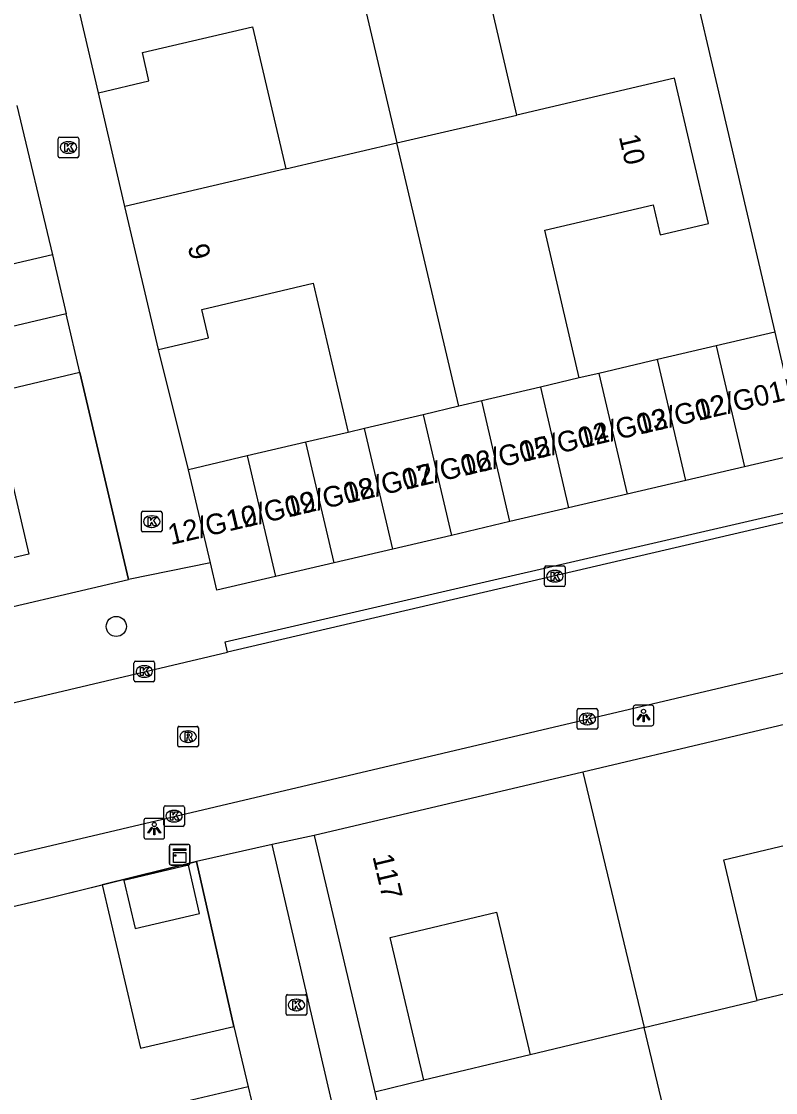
# Model space of a CAD drawing. Extents: x 162990 to 165007, y 383433 to 384336.
# Drawn here: x 164173.2 to 164209.8, y 384013 to 384065 of the extents above; entities that cross this region are included whole.
import ezdxf

# ---------------------------------------------------------------- set-up
doc = ezdxf.new("R2010")
doc.units = 0
for name, color, linetype in [('IMGEO_Boom', 7, 'Continuous'), ('IMGEO_Kast', 7, 'Continuous'), ('IMGEO_Kolk', 7, 'Continuous'), ('IMGEO_Lichtpunt', 7, 'Continuous'), ('IMGEO_Muur', 7, 'Continuous'), ('IMGEO_Pand', 7, 'Continuous'), ('IMGEO_Pand_nummerreeks', 7, 'Continuous'), ('IMGEO_Rijbaan_lokaal_open', 7, 'Continuous'), ('IMGEO_Rioolput', 7, 'Continuous'), ('IMGEO_Voetpad_open', 7, 'Continuous')]:
    doc.layers.add(name, color=color, linetype=linetype)

msp = doc.modelspace()

# ---------------------------------------------------------------- linework, layer by layer
at = {"layer": 'IMGEO_Boom'}
msp.add_circle((164177.761, 384035.63), 0.489, dxfattribs=at)
at = {"layer": 'IMGEO_Kast'}
for p, q in [((164180.337, 384024.129), (164180.337, 384024.97)), ((164180.337, 384024.97), (164180.337, 384024.129)), ((164180.412, 384025.054), (164181.253, 384025.054)), ((164181.253, 384025.054), (164180.412, 384025.054)), ((164181.337, 384024.979), (164181.337, 384024.138)), ((164181.337, 384024.138), (164181.337, 384024.979)), ((164181.262, 384024.054), (164180.421, 384024.054)), ((164180.421, 384024.054), (164181.262, 384024.054))]:
    msp.add_line(p, q, dxfattribs=at)
for points in [[(164180.532, 384024.844), (164181.132, 384024.844), (164181.132, 384024.759), (164180.532, 384024.759), (164180.532, 384024.844)], [(164180.532, 384024.669), (164181.132, 384024.669), (164181.132, 384024.18), (164180.532, 384024.18), (164180.532, 384024.669)]]:
    msp.add_lwpolyline(points, dxfattribs=at)
msp.add_circle((164180.616, 384024.518), 0.0377, dxfattribs=at)
for centre, start, end in [((164180.415, 384024.976), 92.4484, 184.2845), ((164180.415, 384024.976), 92.4484, 184.2845), ((164181.259, 384024.976), 2.4484, 94.2845), ((164181.259, 384024.976), 2.4484, 94.2845), ((164180.415, 384024.132), 182.4484, 274.2845), ((164180.415, 384024.132), 182.4484, 274.2845), ((164181.259, 384024.132), 272.4484, 4.2845), ((164181.259, 384024.132), 272.4484, 4.2845)]:
    msp.add_arc(centre, 0.0779, start, end, dxfattribs=at)
at = {"layer": 'IMGEO_Kolk'}
for p, q in [((164174.939, 384058.444), (164174.939, 384059.296)), ((164175.014, 384059.37), (164175.866, 384059.37)), ((164175.427, 384059.15), (164175.452, 384059.15)), ((164175.94, 384059.296), (164175.94, 384058.444)), ((164175.45, 384058.59), (164175.425, 384058.59)), ((164175.866, 384058.37), (164175.014, 384058.37)), ((164178.981, 384040.292), (164178.981, 384041.144)), ((164179.056, 384041.218), (164179.908, 384041.218)), ((164179.469, 384040.998), (164179.494, 384040.998)), ((164179.982, 384041.144), (164179.982, 384040.292)), ((164179.492, 384040.438), (164179.467, 384040.438)), ((164179.908, 384040.218), (164179.056, 384040.218)), ((164198.545, 384037.641), (164198.545, 384038.493)), ((164198.62, 384038.567), (164199.472, 384038.567)), ((164199.033, 384038.347), (164199.058, 384038.347)), ((164199.546, 384038.493), (164199.546, 384037.641)), ((164199.056, 384037.787), (164199.031, 384037.787)), ((164199.472, 384037.567), (164198.62, 384037.567)), ((164178.62, 384033.019), (164178.62, 384033.871)), ((164178.695, 384033.945), (164179.547, 384033.945)), ((164179.108, 384033.725), (164179.133, 384033.725)), ((164179.621, 384033.871), (164179.621, 384033.019)), ((164179.131, 384033.165), (164179.106, 384033.165)), ((164179.547, 384032.945), (164178.695, 384032.945)), ((164200.123, 384030.715), (164200.123, 384031.567)), ((164200.198, 384031.641), (164201.05, 384031.641)), ((164201.124, 384031.567), (164201.124, 384030.715)), ((164200.611, 384031.421), (164200.636, 384031.421)), ((164201.05, 384030.641), (164200.198, 384030.641)), ((164200.634, 384030.861), (164200.609, 384030.861)), ((164180.063, 384026.001), (164180.063, 384026.853)), ((164180.138, 384026.927), (164180.99, 384026.927)), ((164181.064, 384026.853), (164181.064, 384026.001)), ((164180.551, 384026.707), (164180.576, 384026.707)), ((164180.99, 384025.927), (164180.138, 384025.927)), ((164180.574, 384026.147), (164180.549, 384026.147)), ((164186.002, 384016.838), (164186.002, 384017.69)), ((164186.077, 384017.764), (164186.929, 384017.764)), ((164186.49, 384017.544), (164186.515, 384017.544)), ((164187.003, 384017.69), (164187.003, 384016.838)), ((164186.513, 384016.984), (164186.488, 384016.984)), ((164186.929, 384016.764), (164186.077, 384016.764))]:
    msp.add_line(p, q, dxfattribs=at)
for points in [[(164174.939, 384058.444), (164174.939, 384059.296)], [(164175.014, 384059.37), (164175.866, 384059.37)], [(164175.26, 384059.07), (164175.383, 384059.07), (164175.383, 384058.919), (164175.513, 384059.07), (164175.677, 384059.07), (164175.531, 384058.919), (164175.684, 384058.67), (164175.532, 384058.67), (164175.447, 384058.834), (164175.383, 384058.767), (164175.383, 384058.67), (164175.26, 384058.67), (164175.26, 384059.07)], [(164175.94, 384059.296), (164175.94, 384058.444)], [(164175.866, 384058.37), (164175.014, 384058.37)], [(164178.981, 384040.292), (164178.981, 384041.144)], [(164179.056, 384041.218), (164179.908, 384041.218)], [(164179.302, 384040.918), (164179.425, 384040.918), (164179.425, 384040.767), (164179.555, 384040.918), (164179.719, 384040.918), (164179.573, 384040.767), (164179.726, 384040.518), (164179.574, 384040.518), (164179.489, 384040.682), (164179.425, 384040.615), (164179.425, 384040.518), (164179.302, 384040.518), (164179.302, 384040.918)], [(164179.982, 384041.144), (164179.982, 384040.292)], [(164179.908, 384040.218), (164179.056, 384040.218)], [(164198.545, 384037.641), (164198.545, 384038.493)], [(164198.62, 384038.567), (164199.472, 384038.567)], [(164198.866, 384038.267), (164198.989, 384038.267), (164198.989, 384038.116), (164199.119, 384038.267), (164199.283, 384038.267), (164199.137, 384038.116), (164199.29, 384037.867), (164199.138, 384037.867), (164199.053, 384038.031), (164198.989, 384037.964), (164198.989, 384037.867), (164198.866, 384037.867), (164198.866, 384038.267)], [(164199.546, 384038.493), (164199.546, 384037.641)], [(164199.472, 384037.567), (164198.62, 384037.567)], [(164178.62, 384033.019), (164178.62, 384033.871)], [(164178.695, 384033.945), (164179.547, 384033.945)], [(164178.941, 384033.645), (164179.064, 384033.645), (164179.064, 384033.494), (164179.194, 384033.645), (164179.358, 384033.645), (164179.212, 384033.494), (164179.365, 384033.245), (164179.213, 384033.245), (164179.128, 384033.409), (164179.064, 384033.342), (164179.064, 384033.245), (164178.941, 384033.245), (164178.941, 384033.645)], [(164179.621, 384033.871), (164179.621, 384033.019)], [(164179.547, 384032.945), (164178.695, 384032.945)], [(164200.123, 384030.715), (164200.123, 384031.567)], [(164200.198, 384031.641), (164201.05, 384031.641)], [(164201.124, 384031.567), (164201.124, 384030.715)], [(164200.444, 384031.341), (164200.567, 384031.341), (164200.567, 384031.19), (164200.697, 384031.341), (164200.861, 384031.341), (164200.715, 384031.19), (164200.868, 384030.941), (164200.716, 384030.941), (164200.631, 384031.105), (164200.567, 384031.038), (164200.567, 384030.941), (164200.444, 384030.941), (164200.444, 384031.341)], [(164201.05, 384030.641), (164200.198, 384030.641)], [(164180.063, 384026.001), (164180.063, 384026.853)], [(164180.138, 384026.927), (164180.99, 384026.927)], [(164181.064, 384026.853), (164181.064, 384026.001)], [(164180.384, 384026.627), (164180.507, 384026.627), (164180.507, 384026.476), (164180.637, 384026.627), (164180.801, 384026.627), (164180.655, 384026.476), (164180.808, 384026.227), (164180.656, 384026.227), (164180.571, 384026.391), (164180.507, 384026.324), (164180.507, 384026.227), (164180.384, 384026.227), (164180.384, 384026.627)], [(164180.99, 384025.927), (164180.138, 384025.927)], [(164186.002, 384016.838), (164186.002, 384017.69)], [(164186.077, 384017.764), (164186.929, 384017.764)], [(164186.323, 384017.464), (164186.446, 384017.464), (164186.446, 384017.313), (164186.576, 384017.464), (164186.74, 384017.464), (164186.594, 384017.313), (164186.747, 384017.064), (164186.595, 384017.064), (164186.51, 384017.228), (164186.446, 384017.161), (164186.446, 384017.064), (164186.323, 384017.064), (164186.323, 384017.464)], [(164187.003, 384017.69), (164187.003, 384016.838)], [(164186.929, 384016.764), (164186.077, 384016.764)]]:
    msp.add_lwpolyline(points, dxfattribs=at)
for centre, start, end in [((164175.016, 384059.294), 91.552, 178.448), ((164175.016, 384059.294), 91.552, 178.448), ((164175.864, 384059.294), 1.552, 88.448), ((164175.864, 384059.294), 1.552, 88.448), ((164175.016, 384058.446), 181.552, 268.448), ((164175.016, 384058.446), 181.552, 268.448), ((164175.864, 384058.446), 271.552, 358.448), ((164175.864, 384058.446), 271.552, 358.448), ((164179.058, 384041.142), 91.552, 178.448), ((164179.058, 384041.142), 91.552, 178.448), ((164179.906, 384041.142), 1.552, 88.448), ((164179.906, 384041.142), 1.552, 88.448), ((164179.058, 384040.294), 181.552, 268.448), ((164179.058, 384040.294), 181.552, 268.448), ((164179.906, 384040.294), 271.552, 358.448), ((164179.906, 384040.294), 271.552, 358.448), ((164198.622, 384038.491), 91.552, 178.448), ((164198.622, 384038.491), 91.552, 178.448), ((164199.47, 384038.491), 1.552, 88.448), ((164199.47, 384038.491), 1.552, 88.448), ((164198.622, 384037.643), 181.552, 268.448), ((164198.622, 384037.643), 181.552, 268.448), ((164199.47, 384037.643), 271.552, 358.448), ((164199.47, 384037.643), 271.552, 358.448), ((164178.697, 384033.869), 91.552, 178.448), ((164178.697, 384033.869), 91.552, 178.448), ((164179.545, 384033.869), 1.552, 88.448), ((164179.545, 384033.869), 1.552, 88.448), ((164178.697, 384033.021), 181.552, 268.448), ((164178.697, 384033.021), 181.552, 268.448), ((164179.545, 384033.021), 271.552, 358.448), ((164179.545, 384033.021), 271.552, 358.448), ((164200.2, 384031.565), 91.552, 178.448), ((164200.2, 384031.565), 91.552, 178.448), ((164201.048, 384031.565), 1.552, 88.448), ((164201.048, 384031.565), 1.552, 88.448), ((164200.2, 384030.717), 181.552, 268.448), ((164200.2, 384030.717), 181.552, 268.448), ((164201.048, 384030.717), 271.552, 358.448), ((164201.048, 384030.717), 271.552, 358.448), ((164180.14, 384026.851), 91.552, 178.448), ((164180.14, 384026.851), 91.552, 178.448), ((164180.988, 384026.851), 1.552, 88.448), ((164180.988, 384026.851), 1.552, 88.448), ((164180.14, 384026.003), 181.552, 268.448), ((164180.14, 384026.003), 181.552, 268.448), ((164180.988, 384026.003), 271.552, 358.448), ((164180.988, 384026.003), 271.552, 358.448), ((164186.079, 384017.688), 91.552, 178.448), ((164186.079, 384017.688), 91.552, 178.448), ((164186.927, 384017.688), 1.552, 88.448), ((164186.927, 384017.688), 1.552, 88.448), ((164186.079, 384016.84), 181.552, 268.448), ((164186.079, 384016.84), 181.552, 268.448), ((164186.927, 384016.84), 271.552, 358.448), ((164186.927, 384016.84), 271.552, 358.448)]:
    msp.add_arc(centre, 0.0765, start, end, dxfattribs=at)
for centre, major_axis, ratio, start_param, end_param in [((164175.426, 384058.87), (-0.387, 0.002), 0.722429, 4.712389, 7.853982), ((164175.451, 384058.87), (-0.39, 0.002), 0.717154, 1.570796, 4.712389), ((164179.468, 384040.718), (-0.387, 0.002), 0.722429, 4.712389, 7.853982), ((164179.493, 384040.718), (-0.39, 0.002), 0.717154, 1.570796, 4.712389), ((164199.032, 384038.067), (-0.387, 0.002), 0.722429, 4.712389, 7.853982), ((164199.057, 384038.067), (-0.39, 0.002), 0.717154, 1.570796, 4.712389), ((164179.107, 384033.445), (-0.387, 0.002), 0.722429, 4.712389, 7.853982), ((164179.132, 384033.445), (-0.39, 0.002), 0.717154, 1.570796, 4.712389), ((164200.61, 384031.141), (-0.387, 0.002), 0.722429, 4.712389, 7.853982), ((164200.635, 384031.141), (-0.39, 0.002), 0.717154, 1.570796, 4.712389), ((164180.55, 384026.427), (-0.387, 0.002), 0.722429, 4.712389, 7.853982), ((164180.575, 384026.427), (-0.39, 0.002), 0.717154, 1.570796, 4.712389), ((164186.489, 384017.264), (-0.387, 0.002), 0.722429, 4.712389, 7.853982), ((164186.514, 384017.264), (-0.39, 0.002), 0.717154, 1.570796, 4.712389)]:
    msp.add_ellipse(centre, major_axis=major_axis, ratio=ratio, start_param=start_param, end_param=end_param, dxfattribs=at)
at = {"layer": 'IMGEO_Lichtpunt'}
for p, q in [((164202.851, 384031.711), (164202.851, 384030.904)), ((164202.851, 384031.711), (164202.851, 384030.904)), ((164203.753, 384031.806), (164202.945, 384031.806)), ((164203.753, 384031.806), (164202.945, 384031.806)), ((164203.847, 384030.904), (164203.847, 384031.711)), ((164203.847, 384030.904), (164203.847, 384031.711)), ((164202.945, 384030.81), (164203.753, 384030.81)), ((164202.945, 384030.81), (164203.753, 384030.81)), ((164180.007, 384026.317), (164179.199, 384026.317)), ((164180.007, 384026.317), (164179.199, 384026.317)), ((164179.105, 384026.222), (164179.105, 384025.415)), ((164179.105, 384026.222), (164179.105, 384025.415)), ((164180.101, 384025.415), (164180.101, 384026.222)), ((164180.101, 384025.415), (164180.101, 384026.222)), ((164179.199, 384025.321), (164180.007, 384025.321)), ((164179.199, 384025.321), (164180.007, 384025.321))]:
    msp.add_line(p, q, dxfattribs=at)
for points in [[(164203.225, 384031.375), (164203.264, 384031.347), (164203.076, 384031.085), (164203.038, 384031.112), (164203.225, 384031.375)], [(164203.327, 384031.327), (164203.374, 384031.327), (164203.374, 384031.005), (164203.327, 384031.005), (164203.327, 384031.327)], [(164203.437, 384031.347), (164203.475, 384031.374), (164203.662, 384031.112), (164203.623, 384031.084), (164203.437, 384031.347)], [(164179.479, 384025.886), (164179.518, 384025.858), (164179.33, 384025.596), (164179.292, 384025.623), (164179.479, 384025.886)], [(164179.581, 384025.838), (164179.628, 384025.838), (164179.628, 384025.516), (164179.581, 384025.516), (164179.581, 384025.838)], [(164179.691, 384025.858), (164179.729, 384025.885), (164179.916, 384025.623), (164179.877, 384025.595), (164179.691, 384025.858)]]:
    msp.add_lwpolyline(points, dxfattribs=at)
for centre in [(164203.35, 384031.509), (164179.604, 384026.02)]:
    msp.add_circle(centre, 0.0994, dxfattribs=at)
for centre, start, end in [((164202.945, 384031.711), 90, 180), ((164202.945, 384031.711), 90, 180), ((164203.753, 384031.711), 0, 90), ((164203.753, 384031.711), 0, 90), ((164202.945, 384030.904), 180, 270), ((164202.945, 384030.904), 180, 270), ((164203.753, 384030.904), 270, 0), ((164203.753, 384030.904), 270, 360), ((164179.199, 384026.222), 90, 180), ((164179.199, 384026.222), 90, 180), ((164180.007, 384026.222), 0, 90), ((164180.007, 384026.222), 0, 90), ((164179.199, 384025.415), 180, 270), ((164179.199, 384025.415), 180, 270), ((164180.007, 384025.415), 270, 0), ((164180.007, 384025.415), 270, 360)]:
    msp.add_arc(centre, 0.0946, start, end, dxfattribs=at)
at = {"layer": 'IMGEO_Muur'}
for points in [[(164172.928, 384060.907), (164174.66, 384053.664)], [(164208.559, 384054.87), (164209.723, 384049.905)], [(164175.996, 384047.946), (164178.35, 384037.909)], [(164173.854, 384022.308), (164181.656, 384024.223), (164183.473, 384016.224)]]:
    msp.add_lwpolyline(points, dxfattribs=at)
at = {"layer": 'IMGEO_Pand'}
for points in [[(164197.205, 384060.438), (164195.579, 384067.39), (164200.842, 384068.621), (164201.182, 384067.168), (164203.595, 384067.732), (164201.976, 384074.657), (164194.291, 384072.86)], [(164188.442, 384071.542), (164191.376, 384059.087)], [(164176.898, 384061.524), (164175.266, 384068.505)], [(164176.898, 384061.524), (164179.347, 384062.097), (164179.025, 384063.472), (164184.375, 384064.723), (164185.985, 384057.837)], [(164200.231, 384047.685), (164198.554, 384054.858), (164203.824, 384056.091), (164204.164, 384054.636), (164206.499, 384055.182), (164204.852, 384062.226), (164197.205, 384060.438)], [(164191.376, 384059.087), (164197.205, 384060.438)], [(164174.66, 384053.664), (164166.902, 384051.852), (164165.207, 384059.103)], [(164185.985, 384057.837), (164191.376, 384059.087)], [(164194.385, 384046.31), (164191.376, 384059.087)], [(164185.985, 384057.837), (164178.18, 384056.012)], [(164179.806, 384049.06), (164178.18, 384056.012)], [(164174.66, 384053.664), (164175.328, 384050.805)], [(164179.806, 384049.06), (164182.231, 384049.627), (164181.907, 384051.013), (164187.321, 384052.279), (164189.012, 384045.046)], [(164175.328, 384050.805), (164162.511, 384047.778)], [(164175.996, 384047.946), (164175.328, 384050.805)], [(164209.723, 384049.905), (164206.878, 384049.24)], [(164209.723, 384049.905), (164210.224, 384047.764), (164210.751, 384045.51)], [(164206.878, 384049.24), (164204.032, 384048.574)], [(164206.878, 384049.24), (164208.249, 384043.377)], [(164204.032, 384048.574), (164201.187, 384047.909)], [(164205.403, 384042.711), (164204.032, 384048.574)], [(164175.996, 384047.946), (164171.688, 384046.94), (164173.514, 384039.142), (164169.99, 384038.317), (164169.382, 384038.175)], [(164200.231, 384047.685), (164198.342, 384047.241)], [(164201.187, 384047.909), (164200.231, 384047.685)], [(164201.187, 384047.909), (164202.558, 384042.046)], [(164198.342, 384047.241), (164195.498, 384046.572)], [(164198.342, 384047.241), (164199.713, 384041.38)], [(164195.498, 384046.572), (164194.385, 384046.31)], [(164196.868, 384040.715), (164195.498, 384046.572)], [(164194.385, 384046.31), (164192.653, 384045.903)], [(164192.653, 384045.903), (164189.809, 384045.233)], [(164192.653, 384045.903), (164194.022, 384040.05)], [(164210.751, 384045.51), (164211.094, 384044.042), (164208.249, 384043.377)], [(164189.012, 384045.046), (164186.964, 384044.567)], [(164189.809, 384045.233), (164189.012, 384045.046)], [(164191.177, 384039.384), (164189.809, 384045.233)], [(164186.964, 384044.567), (164184.119, 384043.902)], [(164188.332, 384038.719), (164186.964, 384044.567)], [(164184.119, 384043.902), (164181.273, 384043.236)], [(164184.119, 384043.902), (164185.486, 384038.053)], [(164182.332, 384038.711), (164181.273, 384043.236)], [(164208.249, 384043.377), (164205.403, 384042.711)], [(164205.403, 384042.711), (164202.558, 384042.046)], [(164202.558, 384042.046), (164199.713, 384041.38)], [(164199.713, 384041.38), (164196.868, 384040.715)], [(164196.868, 384040.715), (164194.022, 384040.05)], [(164194.022, 384040.05), (164191.177, 384039.384)], [(164191.177, 384039.384), (164188.332, 384038.719)], [(164188.332, 384038.719), (164185.486, 384038.053)], [(164185.486, 384038.053), (164182.641, 384037.388), (164182.332, 384038.711)], [(164214.083, 384031.794), (164200.399, 384028.561)], [(164200.399, 384028.561), (164187.361, 384025.48)], [(164200.399, 384028.561), (164203.376, 384016.167)], [(164187.361, 384025.48), (164190.301, 384013.036)], [(164208.858, 384017.481), (164207.245, 384024.306), (164212.621, 384025.576), (164214.229, 384018.766)], [(164178.131, 384023.298), (164178.676, 384020.976), (164181.797, 384021.708), (164181.266, 384024.05), (164178.131, 384023.298)], [(164168.83, 384021.131), (164173.854, 384022.308), (164177.078, 384023.099)], [(164177.078, 384023.099), (164178.938, 384015.162), (164183.473, 384016.224)], [(164192.681, 384013.621), (164191.046, 384020.544), (164196.217, 384021.766), (164197.853, 384014.844)], [(164214.229, 384018.766), (164208.858, 384017.481)], [(164203.376, 384016.167), (164208.858, 384017.481)], [(164183.473, 384016.224), (164184.16, 384013.289)], [(164203.376, 384016.167), (164197.853, 384014.844)], [(164206.409, 384003.543), (164203.376, 384016.167)], [(164197.853, 384014.844), (164192.681, 384013.621)], [(164184.16, 384013.289), (164176.468, 384011.485)], [(164192.681, 384013.621), (164190.301, 384013.036)], [(164190.301, 384013.036), (164193.275, 384000.449)]]:
    msp.add_lwpolyline(points, dxfattribs=at)
at = {"layer": 'IMGEO_Rijbaan_lokaal_open'}
for points in [[(164212.528, 384041.226), (164183.166, 384034.381)], [(164169.584, 384031.181), (164183.166, 384034.381)], [(164171.225, 384024.217), (164213.994, 384034.28)]]:
    msp.add_lwpolyline(points, dxfattribs=at)
at = {"layer": 'IMGEO_Rioolput'}
for p, q in [((164180.745, 384029.857), (164180.745, 384030.709)), ((164180.82, 384030.783), (164181.672, 384030.783)), ((164181.233, 384030.563), (164181.258, 384030.563)), ((164181.746, 384030.709), (164181.746, 384029.857)), ((164181.256, 384030.003), (164181.231, 384030.003)), ((164181.672, 384029.783), (164180.82, 384029.783))]:
    msp.add_line(p, q, dxfattribs=at)
for points in [[(164180.745, 384029.857), (164180.745, 384030.709)], [(164180.82, 384030.783), (164181.672, 384030.783)], [(164181.334, 384030.481), (164181.082, 384030.483), (164181.082, 384030.083)], [(164181.26, 384030.402), (164181.206, 384030.402), (164181.206, 384030.321)], [(164181.746, 384030.709), (164181.746, 384029.857)], [(164181.082, 384030.083), (164181.206, 384030.083), (164181.206, 384030.245), (164181.217, 384030.245)], [(164181.206, 384030.321), (164181.258, 384030.321)], [(164181.264, 384030.216), (164181.335, 384030.083), (164181.475, 384030.083), (164181.41, 384030.209)], [(164181.672, 384029.783), (164180.82, 384029.783)]]:
    msp.add_lwpolyline(points, dxfattribs=at)
for centre, radius, start, end in [((164180.822, 384030.707), 0.0765, 91.552, 178.448), ((164180.822, 384030.707), 0.0765, 91.552, 178.448), ((164181.266, 384030.306), 0.0964, 77.0061, 93.1865), ((164181.28, 384030.363), 0.0378, 276.6634, 79.6772), ((164181.333, 384030.371), 0.109, 350.3612, 89.416), ((164181.67, 384030.707), 0.0765, 1.552, 88.448), ((164181.67, 384030.707), 0.0765, 1.552, 88.448), ((164181.216, 384030.192), 0.0533, 26.0293, 88.6989), ((164181.242, 384030.51), 0.19, 274.7715, 282.9687), ((164181.331, 384030.371), 0.112, 277.5842, 350.9817), ((164181.315, 384030.156), 0.108, 29.5134, 73.7905), ((164180.822, 384029.859), 0.0765, 181.552, 268.448), ((164180.822, 384029.859), 0.0765, 181.552, 268.448), ((164181.67, 384029.859), 0.0765, 271.552, 358.448), ((164181.67, 384029.859), 0.0765, 271.552, 358.448)]:
    msp.add_arc(centre, radius, start, end, dxfattribs=at)
for centre, major_axis, ratio, start_param, end_param in [((164181.232, 384030.283), (-0.387, 0.002), 0.722429, 4.712389, 7.853982), ((164181.257, 384030.283), (-0.39, 0.002), 0.717154, 1.570796, 4.712389)]:
    msp.add_ellipse(centre, major_axis=major_axis, ratio=ratio, start_param=start_param, end_param=end_param, dxfattribs=at)
at = {"layer": 'IMGEO_Voetpad_open'}
for points in [[(164199.592, 384093.127), (164208.559, 384054.87), (164209.723, 384049.905)], [(164178.18, 384056.012), (164176.898, 384061.524)], [(164172.928, 384060.907), (164174.66, 384053.664)], [(164181.273, 384043.236), (164179.806, 384049.06)], [(164178.35, 384037.909), (164175.996, 384047.946)], [(164183.166, 384034.381), (164183.05, 384034.876), (164212.427, 384041.655), (164212.528, 384041.226)], [(164182.332, 384038.711), (164178.35, 384037.909)], [(164169.908, 384035.931), (164178.35, 384037.909)], [(164187.361, 384025.48), (164185.328, 384025.042)], [(164185.328, 384025.042), (164181.656, 384024.223)], [(164191.131, 383999.99), (164191.129, 384000), (164185.328, 384025.042)], [(164181.656, 384024.223), (164177.078, 384023.099)], [(164183.473, 384016.224), (164181.656, 384024.223)], [(164184.16, 384013.289), (164185.906, 384005.923)]]:
    msp.add_lwpolyline(points, dxfattribs=at)

# ---------------------------------------------------------------- texts
at = {"layer": 'IMGEO_Pand_nummerreeks'}
for s, rotation, p in [('10', 283.1602, (164202.145, 384059.398)), ('9', 283.1642, (164181.223, 384054.071)), ('12/G01', 13.2525, (164206.003, 384045.605)), ('12/G02', 13.2517, (164203.159, 384044.935)), ('12/G03', 13.2517, (164200.314, 384044.265)), ('12/G04', 13.2517, (164197.469, 384043.595)), ('12/G05', 13.2517, (164194.624, 384042.925)), ('12/G06', 13.2517, (164191.78, 384042.255)), ('12/G07', 13.2517, (164188.935, 384041.585)), ('12/G08', 13.2517, (164186.09, 384040.915)), ('12/G09', 13.2517, (164183.246, 384040.245)), ('12/G10', 13.2517, (164180.401, 384039.575)), ('117', 283.2933, (164190.188, 384024.473))]:
    msp.add_text(s, height=1, rotation=rotation, dxfattribs=at).set_placement(p)

doc.saveas('drawing.dxf')
